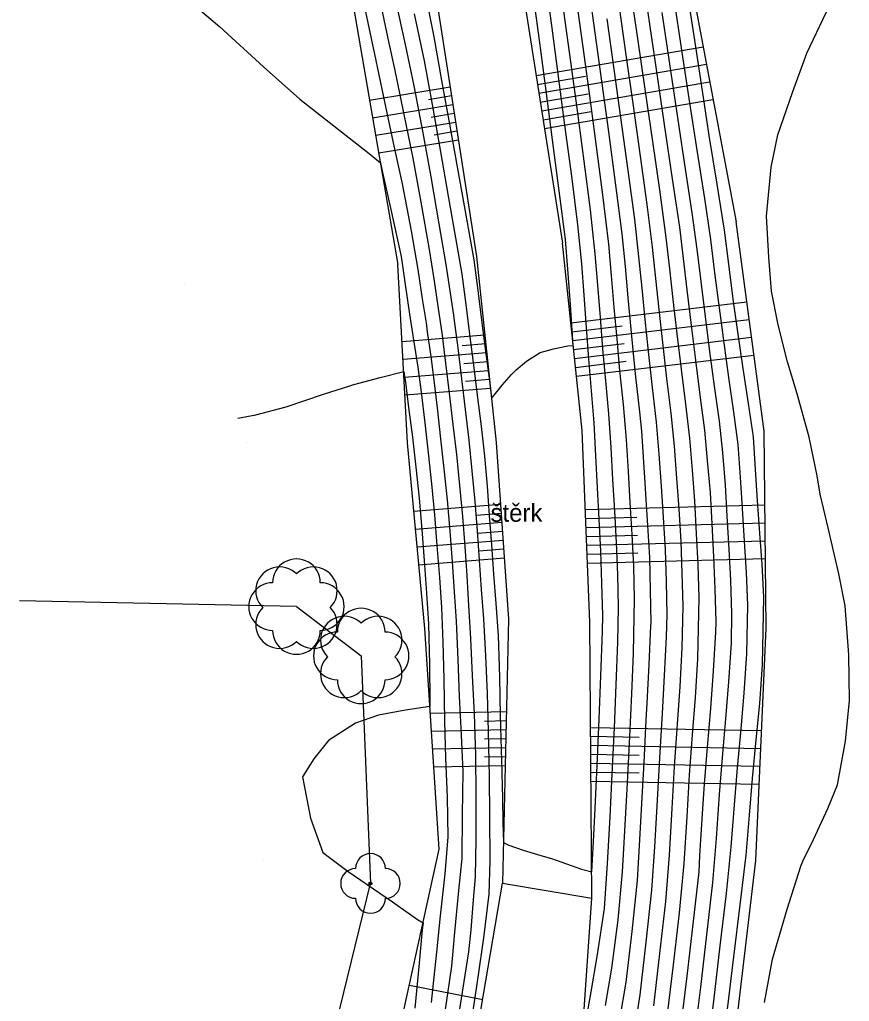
# Model space of a CAD drawing. Extents: x -448957 to -448612, y -1107690 to -1107245.
# Drawn here: x -448746.44 to -448718.6, y -1107469.55 to -1107436.62 of the extents above; entities that cross this region are included whole.
import ezdxf

# ---------------------------------------------------------------- set-up
doc = ezdxf.new("R2010")
doc.units = 0
for name, color, linetype in [('22', 7, 'Continuous'), ('Default', 7, 'Continuous'), ('Vrstva 1', 7, 'Continuous'), ('Vrstva 11', 7, 'Continuous'), ('Vrstva 14', 7, 'Continuous'), ('Vrstva 15', 7, 'Continuous'), ('Vrstva 16', 7, 'Continuous'), ('Vrstva 17', 7, 'Continuous'), ('Vrstva 21', 7, 'Continuous'), ('Vrstva 22', 7, 'Continuous'), ('Vrstva 40', 7, 'Continuous')]:
    doc.layers.add(name, color=color, linetype=linetype)

# ---------------------------------------------------------------- blocks, each defined once
blk = doc.blocks.new('POINT_DISPLAY')
at = {"layer": 'Default'}
blk.add_line((0, 0), (0, 0), dxfattribs=at)
blk = doc.blocks.new('STROM$5')
at = {"layer": '22'}
blk.add_circle((0, 0), 0.5, dxfattribs=at)
for centre, start, end in [((0, 5), 0, 180), ((-5, 0), 90, 270), ((5, 0), 270, 90), ((0, -5), 180, 0)]:
    blk.add_arc(centre, 5, start, end, dxfattribs=at)
blk = doc.blocks.new('KER')
at = {"layer": 'Default'}
for centre, start, end in [((-5.66, 5.31), 44.9958, 225.0042), ((0, 8), 359.9958, 180.0042), ((5.66, 5.31), 314.9989, 135.0011), ((-8, 0), 89.9989, 270.0011), ((8, 0), 269.9989, 90.0011), ((-5.66, -6), 134.9989, 315.0011), ((5.66, -6), 224.9958, 45.0042), ((0, -8), 179.9958, 0.0042)]:
    blk.add_arc(centre, 8, start, end, dxfattribs=at)

msp = doc.modelspace()

# ---------------------------------------------------------------- linework, layer by layer
at = {"layer": 'Vrstva 11'}
for p, q in [((-448729.762, -1107434.346), (-448728.221, -1107444.12)), ((-448732.598, -1107435.026), (-448731.108, -1107444.565)), ((-448727.567, -1107450.405), (-448728.221, -1107444.12)), ((-448731.108, -1107444.565), (-448730.444, -1107450.81)), ((-448727.303, -1107456.83), (-448727.567, -1107450.405)), ((-448730.444, -1107450.81), (-448730.037, -1107456.733)), ((-448730.037, -1107456.733), (-448730.236, -1107465.588)), ((-448727.235, -1107466.085), (-448727.303, -1107456.83)), ((-448730.236, -1107465.588), (-448727.235, -1107466.085))]:
    msp.add_line(p, q, dxfattribs=at)
at = {"layer": 'Vrstva 14'}
for p, q in [((-448724.227, -1107433.707), (-448722.4, -1107443.409)), ((-448735.388, -1107435.326), (-448733.743, -1107444.837)), ((-448721.455, -1107450.422), (-448722.4, -1107443.409)), ((-448733.421, -1107450.818), (-448733.743, -1107444.837)), ((-448721.389, -1107457.034), (-448721.455, -1107450.422)), ((-448732.841, -1107457.043), (-448733.421, -1107450.818)), ((-448732.359, -1107464.446), (-448732.841, -1107457.043)), ((-448721.738, -1107464.829), (-448721.389, -1107457.034)), ((-448734.234, -1107472.988), (-448732.359, -1107464.446)), ((-448722.982, -1107475.329), (-448721.738, -1107464.829)), ((-448731.678, -1107474.069), (-448730.236, -1107465.588)), ((-448727.858, -1107474.971), (-448727.235, -1107466.085))]:
    msp.add_line(p, q, dxfattribs=at)
at = {"layer": 'Vrstva 15'}
for p, q in [((-448729.107, -1107438.499), (-448723.507, -1107437.531)), ((-448729.014, -1107439.092), (-448723.396, -1107438.12)), ((-448729.06, -1107438.795), (-448727.455, -1107438.518)), ((-448731.995, -1107438.885), (-448734.696, -1107439.329)), ((-448728.92, -1107439.685), (-448723.285, -1107438.71)), ((-448731.949, -1107439.181), (-448732.72, -1107439.308)), ((-448728.967, -1107439.388), (-448727.357, -1107439.11)), ((-448728.827, -1107440.277), (-448723.174, -1107439.3)), ((-448731.903, -1107439.478), (-448734.593, -1107439.921)), ((-448731.856, -1107439.774), (-448732.625, -1107439.901)), ((-448728.874, -1107439.981), (-448727.258, -1107439.702)), ((-448731.81, -1107440.071), (-448734.491, -1107440.512)), ((-448731.764, -1107440.367), (-448732.53, -1107440.493)), ((-448731.717, -1107440.663), (-448734.389, -1107441.103)), ((-448727.943, -1107446.793), (-448722.039, -1107446.088)), ((-448727.912, -1107447.091), (-448726.22, -1107446.889)), ((-448727.881, -1107447.389), (-448721.959, -1107446.683)), ((-448730.828, -1107447.203), (-448733.604, -1107447.425)), ((-448730.796, -1107447.501), (-448731.589, -1107447.565)), ((-448727.85, -1107447.688), (-448726.153, -1107447.485)), ((-448727.819, -1107447.986), (-448721.879, -1107447.277)), ((-448730.764, -1107447.8), (-448733.571, -1107448.024)), ((-448727.757, -1107448.583), (-448721.799, -1107447.872)), ((-448730.732, -1107448.098), (-448731.534, -1107448.162)), ((-448727.788, -1107448.285), (-448726.085, -1107448.082)), ((-448730.701, -1107448.396), (-448733.539, -1107448.624)), ((-448730.669, -1107448.695), (-448731.48, -1107448.76)), ((-448730.637, -1107448.993), (-448733.507, -1107449.223)), ((-448730.301, -1107452.889), (-448733.206, -1107453.124)), ((-448727.458, -1107453.053), (-448721.43, -1107452.899)), ((-448730.281, -1107453.189), (-448731.111, -1107453.256)), ((-448727.446, -1107453.353), (-448725.729, -1107453.309)), ((-448730.26, -1107453.488), (-448733.15, -1107453.722)), ((-448730.239, -1107453.787), (-448731.065, -1107453.854)), ((-448727.434, -1107453.653), (-448721.424, -1107453.499)), ((-448730.219, -1107454.087), (-448733.095, -1107454.319)), ((-448727.421, -1107453.953), (-448725.71, -1107453.909)), ((-448727.409, -1107454.252), (-448721.418, -1107454.099)), ((-448730.198, -1107454.386), (-448731.02, -1107454.452)), ((-448730.178, -1107454.685), (-448733.039, -1107454.917)), ((-448727.397, -1107454.552), (-448725.69, -1107454.509)), ((-448727.384, -1107454.852), (-448721.412, -1107454.7)), ((-448730.107, -1107459.843), (-448732.655, -1107459.898)), ((-448730.114, -1107460.144), (-448730.842, -1107460.159)), ((-448727.277, -1107460.359), (-448721.543, -1107460.466)), ((-448730.12, -1107460.444), (-448732.616, -1107460.497)), ((-448727.275, -1107460.659), (-448725.645, -1107460.689)), ((-448730.134, -1107461.044), (-448732.577, -1107461.096)), ((-448730.127, -1107460.744), (-448730.84, -1107460.759)), ((-448727.273, -1107460.959), (-448721.569, -1107461.065)), ((-448730.141, -1107461.344), (-448730.839, -1107461.359)), ((-448727.27, -1107461.259), (-448725.65, -1107461.289)), ((-448730.147, -1107461.645), (-448732.538, -1107461.695)), ((-448727.268, -1107461.559), (-448721.596, -1107461.665)), ((-448727.266, -1107461.859), (-448725.654, -1107461.889)), ((-448727.264, -1107462.159), (-448721.623, -1107462.265)), ((-448730.901, -1107469.497), (-448733.362, -1107469.018))]:
    msp.add_line(p, q, dxfattribs=at)
at = {"layer": 'Vrstva 16'}
for points in [[(-448724.706, -1107470.069), (-448724.496, -1107468.325), (-448724.299, -1107466.577), (-448724.138, -1107464.926), (-448724.042, -1107463.359), (-448723.958, -1107461.955), (-448723.856, -1107460.607), (-448723.76, -1107459.362), (-448723.68, -1107458.064), (-448723.638, -1107456.015), (-448723.669, -1107454.913), (-448723.721, -1107453.855), (-448723.781, -1107452.757), (-448723.866, -1107451.73), (-448723.954, -1107450.66), (-448724.088, -1107449.517), (-448724.235, -1107448.348), (-448724.375, -1107447.155), (-448724.507, -1107446.012), (-448724.625, -1107444.976), (-448724.742, -1107443.93), (-448724.962, -1107442.332), (-448725.196, -1107440.706), (-448725.449, -1107438.954), (-448725.685, -1107437.328), (-448725.926, -1107435.657)], [(-448733.847, -1107435.873), (-448733.504, -1107437.45), (-448733.207, -1107438.838), (-448732.909, -1107440.422), (-448732.646, -1107441.889), (-448732.367, -1107443.476), (-448732.134, -1107444.832), (-448731.878, -1107446.539), (-448731.864, -1107446.632), (-448731.739, -1107447.634), (-448731.609, -1107448.675), (-448731.364, -1107450.729), (-448731.26, -1107451.751), (-448731.159, -1107452.783), (-448731.09, -1107453.765), (-448731.02, -1107454.752), (-448730.95, -1107455.735), (-448730.879, -1107456.722), (-448730.809, -1107457.962), (-448730.747, -1107459.219), (-448730.721, -1107460.501), (-448730.688, -1107462.012), (-448730.675, -1107463.334), (-448730.658, -1107464.837), (-448730.698, -1107465.955), (-448730.872, -1107467.42), (-448731.065, -1107468.744), (-448731.279, -1107470.169)], [(-448727.435, -1107470.243), (-448727.256, -1107469.228), (-448727.048, -1107467.974), (-448726.817, -1107466.431), (-448726.71, -1107464.924), (-448726.623, -1107463.359), (-448726.553, -1107461.934), (-448726.477, -1107460.372), (-448726.417, -1107458.932), (-448726.361, -1107457.502), (-448726.34, -1107456.324), (-448726.365, -1107455.238), (-448726.412, -1107454.171), (-448726.471, -1107453.1), (-448726.532, -1107452.048), (-448726.587, -1107450.977), (-448726.67, -1107449.84), (-448726.772, -1107448.732), (-448726.865, -1107447.662), (-448726.951, -1107446.612), (-448727.036, -1107445.532), (-448727.121, -1107444.482), (-448727.285, -1107443.002), (-448727.496, -1107441.371), (-448727.723, -1107439.665), (-448727.942, -1107438.032), (-448728.173, -1107436.335)], [(-448721.443, -1107469.586), (-448721.174, -1107468.133), (-448720.686, -1107466.454), (-448720.23, -1107465.016), (-448720.154, -1107464.846), (-448719.796, -1107464.122), (-448719.323, -1107463.077), (-448719, -1107462.284), (-448718.723, -1107460.828), (-448718.597, -1107459.464), (-448718.619, -1107457.93), (-448718.742, -1107456.281), (-448718.949, -1107455.205), (-448719.309, -1107453.664), (-448719.578, -1107452.538), (-448719.672, -1107451.923), (-448719.947, -1107450.622), (-448720.347, -1107449.176), (-448720.673, -1107448.104), (-448720.99, -1107446.858), (-448721.215, -1107445.728), (-448721.304, -1107444.593), (-448721.378, -1107443.208), (-448721.221, -1107441.571), (-448721, -1107440.491), (-448720.503, -1107439.065), (-448720.019, -1107437.746), (-448719.369, -1107436.356)]]:
    msp.add_lwpolyline(points, dxfattribs=at)
at = {"layer": 'Vrstva 17'}
for points in [[(-448733.196, -1107436.425), (-448732.864, -1107438.004), (-448732.601, -1107439.473), (-448732.318, -1107441.059), (-448732.057, -1107442.541), (-448731.777, -1107444.127), (-448731.606, -1107445.16), (-448731.465, -1107446.172), (-448731.338, -1107447.169), (-448731.206, -1107448.21), (-448731.082, -1107449.214), (-448730.955, -1107450.255), (-448730.84, -1107451.266), (-448730.752, -1107452.275), (-448730.68, -1107453.251), (-448730.61, -1107454.238), (-448730.539, -1107455.219), (-448730.46, -1107456.205), (-448730.383, -1107457.283), (-448730.339, -1107458.679), (-448730.315, -1107459.964), (-448730.274, -1107461.479), (-448730.24, -1107462.734), (-448730.223, -1107463.546), (-448730.205, -1107464.222), (-448730.021, -1107464.31), (-448729.541, -1107464.481), (-448729.061, -1107464.624), (-448728.561, -1107464.772), (-448728.09, -1107464.942), (-448727.589, -1107465.116), (-448727.241, -1107465.206), (-448727.186, -1107464.194), (-448727.125, -1107463.075), (-448727.06, -1107461.643), (-448726.987, -1107460.082), (-448726.936, -1107458.63), (-448726.883, -1107457.13), (-448726.873, -1107456.604), (-448726.902, -1107455.527), (-448726.94, -1107454.45), (-448726.995, -1107453.379), (-448727.051, -1107452.321), (-448727.099, -1107451.25), (-448727.159, -1107450.148), (-448727.25, -1107449.071), (-448727.338, -1107447.995), (-448727.417, -1107446.944), (-448727.497, -1107445.858), (-448727.577, -1107444.807), (-448727.703, -1107443.501), (-448727.914, -1107441.869), (-448728.139, -1107440.157), (-448728.356, -1107438.524), (-448728.584, -1107436.82), (-448728.807, -1107435.187)], [(-448724.251, -1107470.438), (-448724.036, -1107468.706), (-448723.838, -1107466.958), (-448723.642, -1107465.207), (-448723.609, -1107464.663), (-448723.521, -1107463.262), (-448723.456, -1107462.258), (-448723.355, -1107461.021), (-448723.246, -1107459.724), (-448723.16, -1107458.464), (-448723.076, -1107457.165), (-448723.07, -1107456.816), (-448723.105, -1107455.713), (-448723.144, -1107454.641), (-448723.205, -1107453.537), (-448723.261, -1107452.485), (-448723.352, -1107451.412), (-448723.443, -1107450.386), (-448723.598, -1107449.217), (-448723.752, -1107448.045), (-448723.894, -1107446.876), (-448724.038, -1107445.688), (-448724.163, -1107444.637), (-448724.289, -1107443.587), (-448724.529, -1107441.962), (-448724.786, -1107440.221), (-448725.025, -1107438.596), (-448725.283, -1107436.856), (-448725.521, -1107435.226)], [(-448732.849, -1107435.614), (-448732.544, -1107437.197), (-448732.281, -1107438.661), (-448731.995, -1107440.247), (-448731.447, -1107443.298), (-448731.201, -1107444.676), (-448731.065, -1107445.712), (-448730.937, -1107446.705), (-448730.803, -1107447.746), (-448730.675, -1107448.74), (-448730.602, -1107449.329), (-448730.517, -1107449.221), (-448730.242, -1107448.877), (-448729.937, -1107448.522), (-448729.778, -1107448.37), (-448729.433, -1107448.081), (-448728.977, -1107447.784), (-448728.524, -1107447.664), (-448728.045, -1107447.568), (-448727.864, -1107447.553), (-448727.91, -1107446.881), (-448727.958, -1107446.183), (-448728.034, -1107445.132), (-448728.121, -1107444), (-448728.332, -1107442.366), (-448728.555, -1107440.649), (-448728.77, -1107439.015), (-448728.995, -1107437.305), (-448729.217, -1107435.672)], [(-448726.295, -1107470.157), (-448726.085, -1107468.907), (-448725.883, -1107467.205), (-448725.707, -1107465.493), (-448725.618, -1107463.928), (-448725.538, -1107462.516), (-448725.487, -1107461.538), (-448725.412, -1107460.119), (-448725.38, -1107459.544), (-448725.317, -1107458.252), (-448725.254, -1107456.953), (-448725.252, -1107456.857), (-448725.272, -1107455.754), (-448725.292, -1107454.662), (-448725.358, -1107453.591), (-448725.422, -1107452.542), (-448725.448, -1107452.162), (-448725.518, -1107451.12), (-448725.564, -1107450.429), (-448725.633, -1107449.777), (-448725.758, -1107448.608), (-448725.817, -1107448.056), (-448725.918, -1107447.006), (-448726.019, -1107445.948), (-448726.113, -1107444.898), (-448726.215, -1107443.805), (-448726.429, -1107442.177), (-448726.667, -1107440.387), (-448727.125, -1107437.064), (-448727.354, -1107435.432)], [(-448722.685, -1107469.813), (-448722.478, -1107468.06), (-448722.258, -1107466.307), (-448722.062, -1107464.647), (-448721.953, -1107463.305), (-448721.849, -1107462.072), (-448721.722, -1107460.775), (-448721.603, -1107459.564), (-448721.51, -1107458.266), (-448721.469, -1107455.989), (-448721.518, -1107454.886), (-448721.596, -1107453.857), (-448721.678, -1107452.752), (-448721.743, -1107451.708), (-448721.816, -1107450.61), (-448721.981, -1107449.496), (-448722.161, -1107448.327), (-448722.327, -1107447.17), (-448722.492, -1107446.001), (-448722.643, -1107444.823), (-448722.789, -1107443.68), (-448723.034, -1107442.135), (-448723.296, -1107440.512), (-448723.56, -1107438.789), (-448723.809, -1107437.166), (-448724.072, -1107435.442)], [(-448740.947, -1107435.809), (-448739.716, -1107436.867), (-448738.254, -1107438.206), (-448737.038, -1107439.288), (-448735.895, -1107440.183), (-448734.706, -1107441.116), (-448734.334, -1107441.421), (-448734.285, -1107441.652), (-448733.982, -1107442.992), (-448733.638, -1107444.57), (-448733.498, -1107445.51), (-448733.356, -1107446.498), (-448733.228, -1107447.294), (-448733.079, -1107448.281), (-448732.967, -1107449.122), (-448732.845, -1107450.144), (-448732.729, -1107451.157), (-448732.619, -1107452.195), (-448732.52, -1107453.226), (-448732.434, -1107454.264), (-448732.35, -1107455.334), (-448732.286, -1107456.34), (-448732.24, -1107457.5), (-448732.204, -1107458.738), (-448732.177, -1107460.148), (-448732.153, -1107461.388), (-448732.096, -1107462.699), (-448732.07, -1107464.03), (-448732.17, -1107465.278), (-448732.342, -1107466.777), (-448732.439, -1107467.802), (-448732.516, -1107468.522), (-448732.635, -1107469.588)], [(-448726.775, -1107469.692), (-448726.566, -1107468.44), (-448726.35, -1107466.818), (-448726.208, -1107465.209), (-448726.121, -1107463.644), (-448726.045, -1107462.225), (-448725.966, -1107460.662), (-448725.898, -1107459.234), (-448725.839, -1107457.875), (-448725.806, -1107456.044), (-448725.828, -1107454.949), (-448725.884, -1107453.892), (-448725.947, -1107452.821), (-448726.012, -1107451.774), (-448726.076, -1107450.703), (-448726.181, -1107449.532), (-448726.295, -1107448.393), (-448726.392, -1107447.329), (-448726.485, -1107446.279), (-448726.575, -1107445.207), (-448726.665, -1107444.157), (-448726.866, -1107442.502), (-448727.078, -1107440.873), (-448727.307, -1107439.173), (-448727.529, -1107437.54), (-448727.762, -1107435.85)], [(-448723.56, -1107472.936), (-448723.134, -1107469.444), (-448722.93, -1107467.687), (-448722.718, -1107465.936), (-448722.559, -1107464.367), (-448722.454, -1107462.956), (-448722.351, -1107461.722), (-448722.23, -1107460.425), (-448722.122, -1107459.197), (-448722.032, -1107457.899), (-448722.003, -1107456.265), (-448722.047, -1107455.162), (-448722.112, -1107454.118), (-448722.187, -1107453.014), (-448722.249, -1107451.967), (-448722.328, -1107450.877), (-448722.468, -1107449.793), (-448722.64, -1107448.624), (-448722.802, -1107447.461), (-448722.959, -1107446.293), (-448723.108, -1107445.111), (-448723.247, -1107443.999), (-448723.452, -1107442.619), (-448723.707, -1107440.996), (-448723.969, -1107439.267), (-448724.215, -1107437.643), (-448724.476, -1107435.913)], [(-448734.867, -1107436.206), (-448734.533, -1107437.785), (-448734.236, -1107439.17), (-448733.904, -1107440.749), (-448733.605, -1107442.126), (-448733.298, -1107443.709), (-448733.077, -1107445.003), (-448732.927, -1107445.99), (-448732.802, -1107446.792), (-448732.759, -1107447.092), (-448732.645, -1107447.925), (-448732.552, -1107448.62), (-448732.432, -1107449.637), (-448732.311, -1107450.678), (-448732.204, -1107451.693), (-448732.097, -1107452.731), (-448732.006, -1107453.783), (-448731.921, -1107454.813), (-448731.858, -1107455.814), (-448731.796, -1107456.802), (-448731.74, -1107458.08), (-448731.689, -1107459.317), (-448731.627, -1107460.611), (-448731.568, -1107461.853), (-448731.586, -1107463.277), (-448731.603, -1107464.761), (-448731.709, -1107465.837), (-448731.857, -1107467.349), (-448731.952, -1107468.37), (-448732.157, -1107469.818)], [(-448734.346, -1107436.04), (-448734.047, -1107437.41), (-448733.859, -1107438.277), (-448733.564, -1107439.687), (-448733.243, -1107441.268), (-448732.981, -1107442.739), (-448732.7, -1107444.326), (-448732.541, -1107445.318), (-448732.393, -1107446.305), (-448732.275, -1107447.128), (-448732.143, -1107448.146), (-448732.02, -1107449.155), (-448731.897, -1107450.196), (-448731.783, -1107451.211), (-448731.678, -1107452.248), (-448731.581, -1107453.284), (-448731.504, -1107454.29), (-448731.438, -1107455.281), (-448731.372, -1107456.268), (-448731.308, -1107457.381), (-448731.249, -1107458.617), (-448731.184, -1107459.902), (-448731.139, -1107461.29), (-448731.127, -1107462.615), (-448731.128, -1107464.108), (-448731.151, -1107465.378), (-448731.219, -1107466.144), (-448731.304, -1107467.146), (-448731.382, -1107467.885), (-448731.593, -1107469.244), (-448731.816, -1107470.665)], [(-448725.16, -1107469.7), (-448724.956, -1107467.944), (-448724.76, -1107466.196), (-448724.633, -1107464.645), (-448724.54, -1107463.079), (-448724.459, -1107461.669), (-448724.279, -1107458.992), (-448724.205, -1107457.693), (-448724.176, -1107456.296), (-448724.204, -1107455.193), (-448724.245, -1107454.124), (-448724.307, -1107453.035), (-448724.384, -1107452.001), (-448724.467, -1107450.93), (-448724.58, -1107449.822), (-448724.72, -1107448.653), (-448724.856, -1107447.455), (-448724.977, -1107446.343), (-448725.089, -1107445.3), (-448725.199, -1107444.252), (-448725.38, -1107442.823), (-448725.607, -1107441.197), (-448725.855, -1107439.432), (-448726.087, -1107437.804), (-448726.325, -1107436.126)], [(-448725.818, -1107470.614), (-448725.615, -1107469.331), (-448725.416, -1107467.563), (-448725.222, -1107465.816), (-448725.129, -1107464.365), (-448725.038, -1107462.799), (-448724.961, -1107461.384), (-448724.872, -1107459.898), (-448724.798, -1107458.622), (-448724.73, -1107457.323), (-448724.714, -1107456.576), (-448724.738, -1107455.474), (-448724.768, -1107454.393), (-448724.832, -1107453.313), (-448724.903, -1107452.272), (-448724.981, -1107451.201), (-448725.071, -1107450.126), (-448725.204, -1107448.958), (-448725.337, -1107447.756), (-448725.447, -1107446.674), (-448725.554, -1107445.624), (-448725.656, -1107444.575), (-448725.797, -1107443.314), (-448726.018, -1107441.687), (-448726.261, -1107439.909), (-448726.49, -1107438.279), (-448726.725, -1107436.595)], [(-448724.015, -1107472.563), (-448723.585, -1107469.076), (-448723.382, -1107467.314), (-448723.177, -1107465.565), (-448723.057, -1107464.087), (-448722.955, -1107462.607), (-448722.853, -1107461.371), (-448722.738, -1107460.074), (-448722.641, -1107458.83), (-448722.554, -1107457.532), (-448722.536, -1107456.54), (-448722.576, -1107455.437), (-448722.628, -1107454.38), (-448722.696, -1107453.276), (-448722.755, -1107452.226), (-448722.84, -1107451.145), (-448722.956, -1107450.089), (-448723.119, -1107448.921), (-448723.277, -1107447.753), (-448723.427, -1107446.584), (-448723.573, -1107445.4), (-448723.705, -1107444.318), (-448723.871, -1107443.103), (-448724.118, -1107441.479), (-448724.879, -1107436.384)], [(-448739.122, -1107449.988), (-448738.518, -1107449.881), (-448737.494, -1107449.612), (-448736.238, -1107449.185), (-448735.358, -1107448.905), (-448735.22, -1107448.856), (-448734.337, -1107448.626), (-448733.55, -1107448.429), (-448733.524, -1107448.586), (-448733.493, -1107448.781), (-448733.385, -1107449.632), (-448733.261, -1107450.631), (-448733.149, -1107451.635), (-448733.036, -1107452.673), (-448732.946, -1107453.727), (-448732.861, -1107454.765), (-448732.785, -1107455.855), (-448732.716, -1107456.885), (-448732.69, -1107458.255), (-448732.671, -1107459.496), (-448732.671, -1107459.585), (-448732.671, -1107459.66), (-448733.496, -1107459.788), (-448734.399, -1107459.955), (-448735.166, -1107460.219), (-448736.08, -1107460.795), (-448736.565, -1107461.42), (-448736.947, -1107462.017), (-448736.681, -1107463.4), (-448736.264, -1107464.562), (-448735.41, -1107465.197), (-448733.932, -1107466.208), (-448733.091, -1107466.802), (-448732.901, -1107466.916), (-448732.922, -1107467.066), (-448732.947, -1107467.263), (-448733.032, -1107468.266), (-448733.177, -1107469.78)]]:
    msp.add_lwpolyline(points, dxfattribs=at)
at = {"layer": 'Vrstva 21'}
for p, q in [((-448737.149, -1107456.309), (-448746.439, -1107456.114)), ((-448737.149, -1107456.309), (-448734.977, -1107457.963)), ((-448734.977, -1107457.963), (-448734.666, -1107465.594)), ((-448736.309, -1107472.338), (-448734.666, -1107465.594))]:
    msp.add_line(p, q, dxfattribs=at)

# ---------------------------------------------------------------- block references
at = {"layer": 'Vrstva 1', "xscale": 0.1, "yscale": 0.10000000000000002}
for p in [(-448722.4, -1107443.409), (-448728.221, -1107444.12), (-448731.108, -1107444.565), (-448733.743, -1107444.837), (-448727.567, -1107450.405), (-448721.455, -1107450.422), (-448733.421, -1107450.818), (-448730.444, -1107450.81), (-448737.149, -1107456.309), (-448730.037, -1107456.733), (-448732.841, -1107457.043), (-448727.303, -1107456.83), (-448721.389, -1107457.034), (-448734.977, -1107457.963), (-448734.977, -1107457.963), (-448732.359, -1107464.446), (-448721.738, -1107464.829), (-448734.666, -1107465.594), (-448734.666, -1107465.594), (-448730.236, -1107465.588), (-448730.236, -1107465.588), (-448727.235, -1107466.085), (-448727.235, -1107466.085)]:
    msp.add_blockref('POINT_DISPLAY', p, dxfattribs=at)
at = {"layer": 'Vrstva 14', "xscale": 0.1, "yscale": 0.10000000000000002}
for p in [(-448740.921, -1107445.508), (-448738.791, -1107450.812), (-448738.285, -1107457.664), (-448738.258, -1107464.777)]:
    msp.add_blockref('POINT_DISPLAY', p, dxfattribs=at)
at = {"layer": 'Vrstva 21', "xscale": 0.1, "yscale": 0.10000000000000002}
for p in [(-448737.149, -1107456.309), (-448734.977, -1107457.963)]:
    msp.add_blockref('KER', p, dxfattribs=at)
at = {"layer": 'Vrstva 22', "xscale": 0.1, "yscale": 0.10000000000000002}
msp.add_blockref('STROM$5', (-448734.666, -1107465.594), dxfattribs=at)

# ---------------------------------------------------------------- texts
at = {"layer": 'Vrstva 40'}
msp.add_text('štěrk', height=0.6, dxfattribs=at).set_placement((-448730.635, -1107453.463))

doc.saveas('drawing.dxf')
